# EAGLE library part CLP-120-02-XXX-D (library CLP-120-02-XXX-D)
050" (1,27mm) Low Profile, Tiger Claw Contact Socket Strip, 40 PINS.
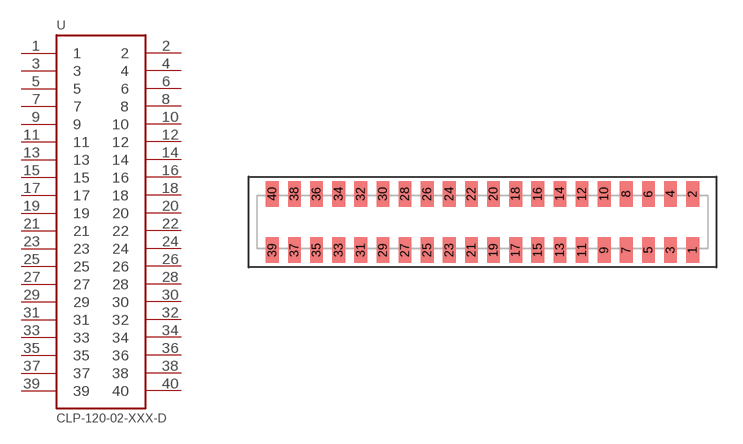
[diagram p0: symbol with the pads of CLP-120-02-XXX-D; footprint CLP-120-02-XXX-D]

Designator prefix -

## CLP-120-02-XXX-D  [CLP-120-02-XXX-D]
1  1
2  2
3  3
4  4
5  5
6  6
7  7
8  8
9  9
10  10
11  11
12  12
13  13
14  14
15  15
16  16
17  17
18  18
19  19
20  20
21  21
22  22
23  23
24  24
25  25
26  26
27  27
28  28
29  29
30  30
31  31
32  32
33  33
34  34
35  35
36  36
37  37
38  38
39  39
40  40

## Footprint CLP-120-02-XXX-D (pad centres in mm)
050" (1,27mm) Low Profile, Tiger Claw Contact Socket Strip, 40 PINS.
smd 0.737 x 1.473: 1 12.065,-1.613; 2 12.065,1.613; 3 10.795,-1.613; 4 10.795,1.613; 5 9.525,-1.613; 6 9.525,1.613; 7 8.255,-1.613; 8 8.255,1.613; 9 6.985,-1.613; 10 6.985,1.613; 11 5.715,-1.613; 12 5.715,1.613; 13 4.445,-1.613; 14 4.445,1.613; 15 3.175,-1.613; 16 3.175,1.613; 17 1.905,-1.613; 18 1.905,1.613; 19 0.635,-1.613; 20 0.635,1.613; 21 -0.635,-1.613; 22 -0.635,1.613; 23 -1.905,-1.613; 24 -1.905,1.613; 25 -3.175,-1.613; 26 -3.175,1.613; 27 -4.445,-1.613; 28 -4.445,1.613; 29 -5.715,-1.613; 30 -5.715,1.613; 31 -6.985,-1.613; 32 -6.985,1.613; 33 -8.255,-1.613; 34 -8.255,1.613; 35 -9.525,-1.613; 36 -9.525,1.613; 37 -10.795,-1.613; 38 -10.795,1.613; 39 -12.065,-1.613; 40 -12.065,1.613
